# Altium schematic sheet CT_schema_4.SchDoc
size 279 x 211 mm
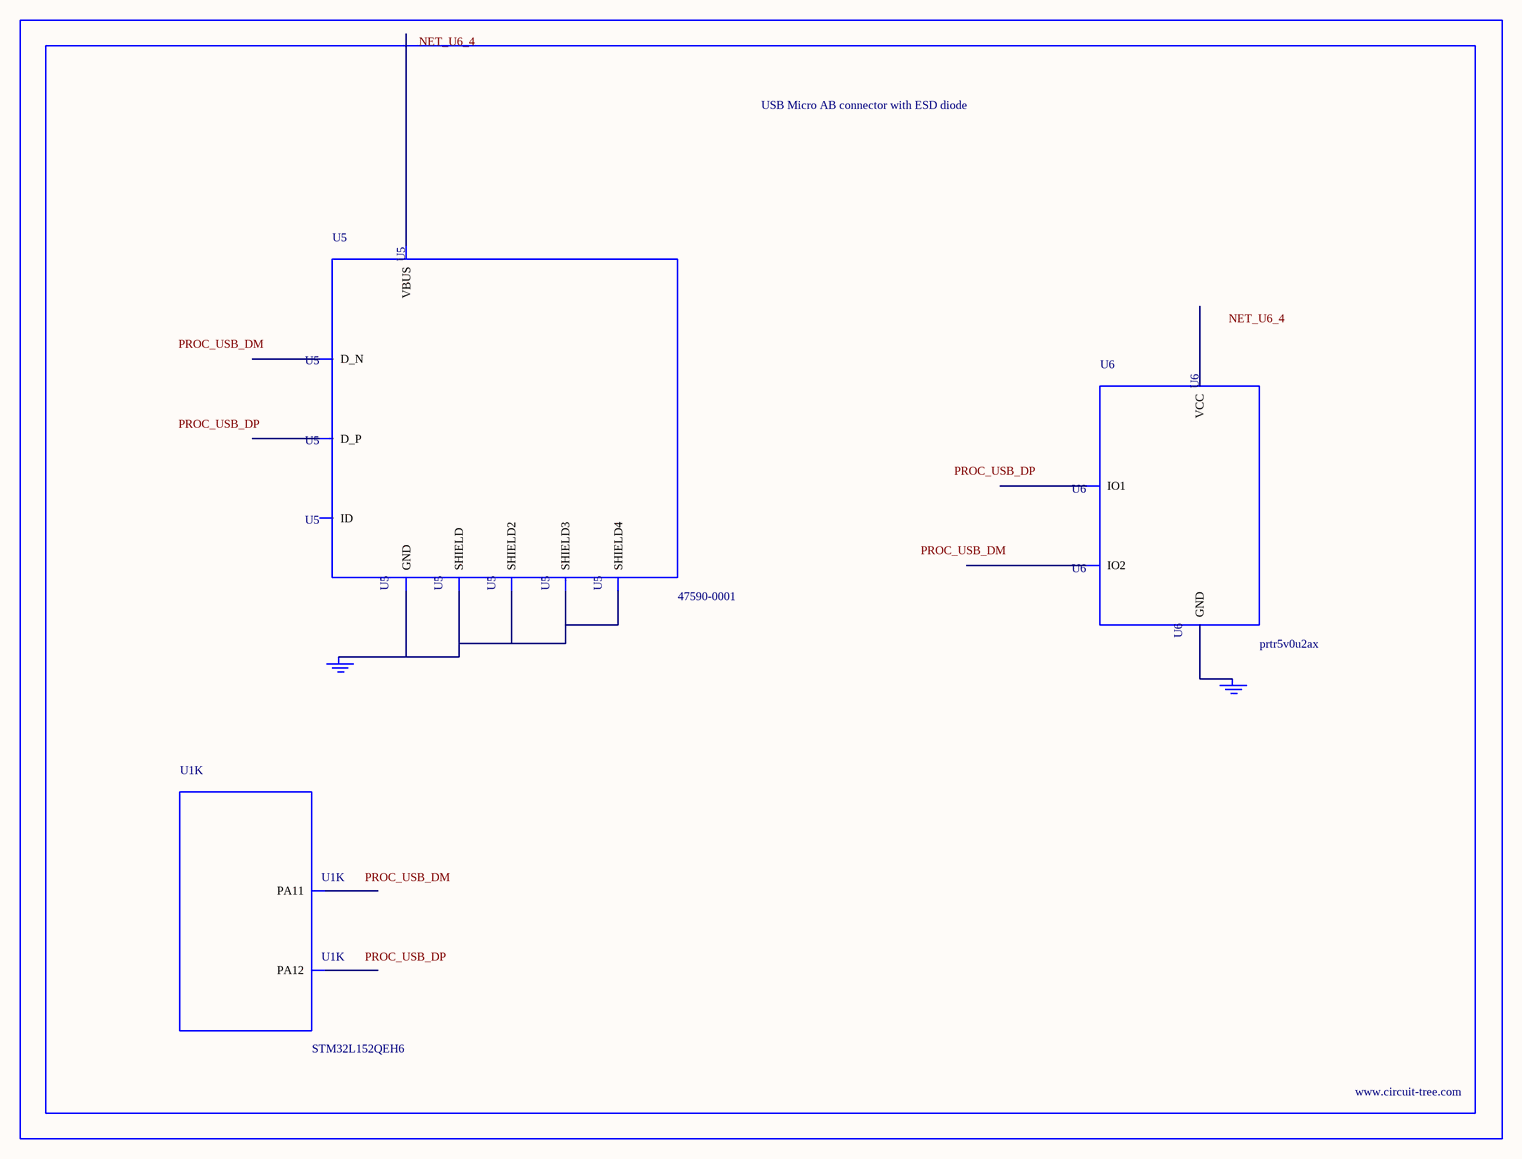
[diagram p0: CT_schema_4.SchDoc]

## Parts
BORDER3  (no value)
GND_INSTANCE_3_0  (no value)
GND_INSTANCE_3_1  (no value)
U1  STM32L152QEH6  [UFBGA132]  (part K of 12)
U5  47590-0001  [MICRO_USB_AB]
U6  prtr5v0u2ax  [SOT143B]

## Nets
NetGND_INSTANCE_3_0_0: GND_INSTANCE_3_0.0(GND) U5.5(GND) U5.6(SHIELD) U5.7(SHIELD2) U5.8(SHIELD3) U5.9(SHIELD4)
NetGND_INSTANCE_3_1_0: GND_INSTANCE_3_1.0(GND) U6.1(GND)

Not connected (* = marked no-connect by the designer): U1 A12(PA12) B12(PA11); U5 1(VBUS) 2(D_N) 3(D_P) 4(ID); U6 2(IO1) 3(IO2) 4(VCC)

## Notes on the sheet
- Labels drawn without touching a wire or pin: NET_U6_4, PROC_USB_DM, PROC_USB_DP

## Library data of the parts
BORDER3 = BORDER_PAGE3
GND_INSTANCE_3_0 GND_INSTANCE_3_1 = GND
